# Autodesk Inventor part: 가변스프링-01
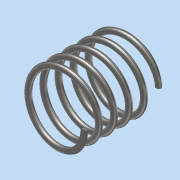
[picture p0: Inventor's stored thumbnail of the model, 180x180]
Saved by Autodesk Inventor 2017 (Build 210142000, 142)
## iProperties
Part Number: 가변스프링-01
Material: 강철, 연강
Document SubType Name: Modeling
Designer: MRC
Mass: 8.3874 g
Surface Area: 21.6623 cm^2
Volume: 1.06846 cm^3
Density: 7.85 g/cm^3
Appearance: 반연마
Author: MRC
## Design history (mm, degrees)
sketch "스케치1"
  geometry: L1 (0, 0)-(0, 26.358); L2 (0, 0)-(11, 0); L3 (0, 26.358)-(11, 26.358); C1 r 1 at (11, 0)
  constraints: 6 end point, 2 horizontal, 1 centre point, 1 coincident, 1 vertical
  dimensions: "d0" = 26.35829 distance of L1.start L1.end (derived); "d1" = 11 distance of L1.start L2.end; "d2" = 2 diameter of C1
feature "코일1" sketch "스케치1" pitch "d3" = 10; turns "d5" = 5; dims "d4" = 26.35829 (= d0), "d6" = 0, angle "d7" = 90 deg, angle "d8" = 90 deg, "d9" = 0, "d10" = 0
sketch "스케치2"
  geometry: L1 (26.358, 15)-(0, 15); L2 (0, 15)-(0, -15); L3 (0, -15)-(26.358, -15); L4 (26.358, -15)-(26.358, 15); 2 further points
  constraints: 8 end point, 2 parallel, 1 coincident, 1 horizontal, 1 midpoint, 1 perpendicular
  dimensions: "d11" = 26.35829 distance of L1.start L1.end (= d0); "d12" = 30 distance of L3.end L1.start
extrude "돌출1" sketch "스케치2" stored distance "d13" = 0; taper "d14" = 0 deg
node "솔리드1"
